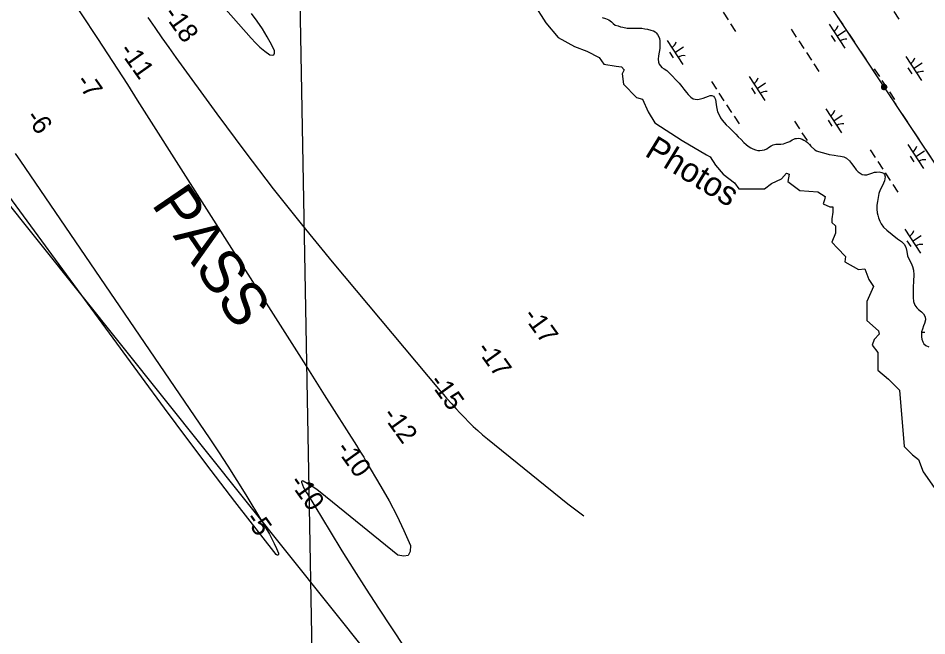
# Model space of a CAD drawing. Extents: x 3945642 to 3966284, y 206476 to 228921.
# Drawn here: x 3956476 to 3958060, y 216052 to 217128 of the extents above; entities that cross this region are included whole.
import ezdxf

# ---------------------------------------------------------------- set-up
doc = ezdxf.new("R2010")
doc.units = 0
for name, color, linetype in [('V-GRID-MAJR', 7, 'Continuous'), ('V-RIVR-EDGE', 7, 'Continuous'), ('V-RIVR-IDEN', 7, 'Continuous'), ('V-RIVR-RANG', 7, 'Continuous'), ('V-TOPO-DPTH', 7, 'Continuous'), ('V-TOPO-MINR', 7, 'Continuous'), ('V-UTIL-LINE', 7, 'Continuous'), ('V-WETL-SWMP', 7, 'Continuous')]:
    doc.layers.add(name, color=color, linetype=linetype)

msp = doc.modelspace()

# ---------------------------------------------------------------- linework, layer by layer
at = {"layer": 'V-GRID-MAJR'}
msp.add_spline([(3957114.3, 209221.5), (3957056.9, 212329.8), (3956944.9, 218389.8), (3956833, 224449.7), (3956787.8, 226894.5)], degree=3, dxfattribs=at)
at = {"layer": 'V-RIVR-EDGE'}
msp.add_lwpolyline([(3957374.4, 217153.2), (3957395.8, 217120), (3957417.2, 217093.9), (3957445.7, 217078.4), (3957467, 217070.1), (3957488.4, 217059.4), (3957496.7, 217047.6), (3957518.1, 217044), (3957527.6, 217042.8), (3957532.3, 217038.1), (3957528.8, 217031), (3957531.2, 217013.1), (3957553.7, 216989.4), (3957564.4, 216987), (3957573.9, 216964.5), (3957585.8, 216945.5), (3957633.3, 216914.6), (3957676, 216889.7), (3957681.9, 216886.1), (3957691.4, 216871.9), (3957704.5, 216856.4), (3957724.7, 216841), (3957731.8, 216830.3), (3957776.9, 216830.3), (3957788.8, 216839.8), (3957806.6, 216848.1), (3957814.9, 216857.6), (3957819.6, 216856.4), (3957817.3, 216843.4), (3957838.6, 216827.9), (3957869.5, 216825.6), (3957882.6, 216817.3), (3957881.4, 216811.3), (3957879, 216804.2), (3957890.9, 216799.4), (3957895.6, 216799.4), (3957895.6, 216789.9), (3957894.4, 216778.1), (3957894.4, 216772.1), (3957900.4, 216766.2), (3957900.4, 216753.1), (3957900.4, 216753.1), (3957894.4, 216737.7), (3957903.9, 216727), (3957918.2, 216712.8), (3957917, 216703.3), (3957940.7, 216690.2), (3957951.4, 216691.4), (3957958.6, 216672.4), (3957966.9, 216660.5), (3957955, 216634.4), (3957955, 216601.2), (3957975.2, 216583.4), (3957976.4, 216577.4), (3957968.1, 216567.9), (3957964.5, 216558.4), (3957974, 216545.4), (3957974, 216527.6), (3957974, 216514.5), (3957993, 216499.1), (3958012, 216480.1), (3958020.3, 216381.5), (3958034.5, 216367.3), (3958045.2, 216359), (3958053.5, 216337.6), (3958072.5, 216310.3)], dxfattribs=at)
at = {"layer": 'V-TOPO-DPTH'}
msp.add_line((3957463.9, 215548.9), (3955413.9, 218111.3), dxfattribs=at)
for points in [[(3956500.5, 217265.1), (3956614.5, 217092.2), (3956632, 217065.5), (3956649.4, 217038.9), (3956666.6, 217012.1), (3956683.7, 216985.2), (3956880.3, 216675.7), (3956912.6, 216624.8), (3956945, 216573.8), (3956977.3, 216522.9), (3957009.6, 216471.9), (3957065.8, 216383.3), (3957070, 216376.6), (3957074.2, 216369.9), (3957078.3, 216363.2), (3957082.3, 216356.4), (3957108.4, 216312.2), (3957122.5, 216287.1), (3957136, 216261.6), (3957148.5, 216235.6), (3957160.2, 216209.3), (3957159.3, 216199), (3957155.6, 216192.2), (3957148.1, 216190.6), (3957137.9, 216192.5), (3957002.3, 216302.5), (3956997, 216306.6), (3956991.5, 216310.5), (3956985.9, 216314), (3956980.1, 216317.4), (3956972.6, 216321.6), (3956971.4, 216321.7), (3956970.5, 216321.4), (3956970, 216320.6), (3956969.9, 216319.4), (3956971.5, 216314.9), (3956973.6, 216310.6), (3956977.8, 216303.1), (3956978.2, 216302.3), (3956979.1, 216300.7), (3956979.6, 216300), (3957019.7, 216233.9), (3957040.4, 216200.3), (3957061.3, 216166.8), (3957082.7, 216133.5), (3957104.3, 216100.4), (3957397.5, 215656.7)], [(3956838.4, 217142.7), (3956882.1, 217093.1), (3956889.6, 217085.1), (3956897.5, 217077.4), (3956905.9, 217070.4), (3956914.7, 217063.7), (3956918.7, 217063.2), (3956921.6, 217064), (3956922.8, 217066.7), (3956923, 217070.7), (3956918.2, 217080.6), (3956910.4, 217095.2), (3956902, 217109.3), (3956892.6, 217122.8), (3956882.6, 217135.9)]]:
    msp.add_lwpolyline(points, dxfattribs=at)
at = {"layer": 'V-TOPO-MINR'}
for points in [[(3956500.5, 217265.1), (3956614.5, 217092.2), (3956632, 217065.5), (3956649.4, 217038.9), (3956666.6, 217012.1), (3956683.7, 216985.2), (3956880.3, 216675.7), (3956912.6, 216624.8), (3956945, 216573.8), (3956977.3, 216522.9), (3957009.6, 216471.9), (3957065.8, 216383.3), (3957070, 216376.6), (3957074.2, 216369.9), (3957078.3, 216363.2), (3957082.3, 216356.4), (3957108.4, 216312.2), (3957122.5, 216287.1), (3957136, 216261.6), (3957148.5, 216235.6), (3957160.2, 216209.3), (3957159.3, 216199), (3957155.6, 216192.2), (3957148.1, 216190.6), (3957137.9, 216192.5), (3957002.3, 216302.5), (3956997, 216306.6), (3956991.5, 216310.5), (3956985.9, 216314), (3956980.1, 216317.4), (3956972.6, 216321.6), (3956971.4, 216321.7), (3956970.5, 216321.4), (3956970, 216320.6), (3956969.9, 216319.4), (3956971.5, 216314.9), (3956973.6, 216310.6), (3956977.8, 216303.1), (3956978.2, 216302.3), (3956979.1, 216300.7), (3956979.6, 216300), (3957019.7, 216233.9), (3957040.4, 216200.3), (3957061.3, 216166.8), (3957082.7, 216133.5), (3957104.3, 216100.4), (3957397.5, 215656.7)], [(3956838.4, 217142.7), (3956882.1, 217093.1), (3956889.6, 217085.1), (3956897.5, 217077.4), (3956905.9, 217070.4), (3956914.7, 217063.7), (3956918.7, 217063.2), (3956921.6, 217064), (3956922.8, 217066.7), (3956923, 217070.7), (3956918.2, 217080.6), (3956910.4, 217095.2), (3956902, 217109.3), (3956892.6, 217122.8), (3956882.6, 217135.9)], [(3956702.4, 217128.9), (3956714.3, 217111.3), (3956726.4, 217093.8), (3956738.6, 217076.5), (3956751, 217059.2), (3956822.3, 216961.3), (3956871.1, 216895.7), (3956920.8, 216830.8), (3956971.8, 216766.9), (3957023.6, 216703.7), (3957211.8, 216478.8), (3957214.5, 216475.6), (3957217.2, 216472.4), (3957220, 216469.3), (3957222.8, 216466.1), (3957231.7, 216456.1), (3957239, 216448), (3957246.4, 216440), (3957254, 216432.2), (3957261.6, 216424.4), (3957269.4, 216416.8), (3957277.4, 216409.4), (3957285.6, 216402.3), (3957293.9, 216395.3), (3957434.3, 216282.2), (3957455, 216266.4), (3957462.1, 216261.3)], [(3956903.4, 216247.6), (3956904.8, 216245.1), (3956906.3, 216242.7), (3956914, 216229), (3956918.4, 216220.9), (3956922.5, 216212.7), (3956926.4, 216204.3), (3956930, 216195.9), (3956929.6, 216193.9), (3956928.9, 216192.7), (3956927.4, 216192.6), (3956925.6, 216193.4), (3956854, 216286.2), (3956812.8, 216340), (3956771.8, 216394.1), (3956731.2, 216448.4), (3956690.9, 216503), (3956367, 216944.4)], [(3956470.8, 216892.3), (3956480.5, 216878.7), (3956809, 216396.7), (3956825.4, 216372.3), (3956841.5, 216347.7), (3956857.3, 216322.8), (3956872.8, 216297.8), (3956900.5, 216252.4), (3956902, 216250), (3956903.4, 216247.6)]]:
    msp.add_lwpolyline(points, dxfattribs=at)
at = {"layer": 'V-UTIL-LINE'}
for points in [[(3958881.3, 222827.3), (3957109.9, 218327), (3961480.2, 211741.6)], [(3957903.7, 217130.8), (3957913.1, 217116.6)], [(3957924.2, 217100), (3957933.6, 217085.8)], [(3957944.6, 217069.1), (3957954, 217055)], [(3957965.1, 217038.3), (3957974.5, 217024.1)], [(3957985.3, 217007.9), (3957985.8, 217009.2), (3957984.7, 217009), (3957984.2, 217007.7), (3957985.1, 217006.6), (3957986.6, 217007.4), (3957987.1, 217009.7), (3957985.3, 217010.8), (3957983, 217010.1), (3957982.4, 217007.9), (3957983.2, 217005.8), (3957985.5, 217005.1), (3957987.9, 217006.5), (3957989, 217010.4), (3957987.8, 217011.6), (3957986.2, 217012.3), (3957984.4, 217012.3), (3957982.8, 217011.7), (3957981.5, 217010.4), (3957980.9, 217008.8), (3957980.8, 217007), (3957981.5, 217005.4), (3957982.8, 217004.2), (3957984.4, 217003.5), (3957986.1, 217003.5), (3957987.8, 217004.2), (3957989, 217005.4), (3957989.7, 217007), (3957989.7, 217008.8), (3957989, 217010.4)], [(3957996, 216991.6), (3958005.4, 216977.5)], [(3958016.5, 216960.8), (3958025.9, 216946.6)], [(3958037, 216930), (3958046.4, 216915.8)], [(3958057.4, 216899.1), (3958066.8, 216885)]]:
    msp.add_lwpolyline(points, dxfattribs=at)
at = {"layer": 'V-WETL-SWMP'}
for p, q in [((3957704.6, 217138.2), (3957713.4, 217124.8)), ((3958002, 217139.3), (3958010.8, 217125.9)), ((3957493.7, 217129), (3957499.7, 217127.4)), ((3957499.7, 217127.4), (3957505.4, 217124.9)), ((3957505.4, 217124.9), (3957509.9, 217121.3)), ((3957509.9, 217121.3), (3957513.3, 217118.3)), ((3957513.3, 217118.3), (3957516.6, 217115.9)), ((3957717.7, 217118.1), (3957726.5, 217104.7)), ((3957516.6, 217115.9), (3957521.5, 217114.2)), ((3957521.5, 217114.2), (3957525.6, 217113)), ((3957525.6, 217113), (3957529.8, 217112)), ((3957529.8, 217112), (3957537.7, 217110.5)), ((3957537.7, 217110.5), (3957556.9, 217110.4)), ((3957556.9, 217110.4), (3957563.1, 217110.2)), ((3957563.1, 217110.2), (3957568.2, 217109.4)), ((3957568.2, 217109.4), (3957572.8, 217108.5)), ((3957572.8, 217108.5), (3957578.5, 217107)), ((3957578.5, 217107), (3957583.1, 217105.6)), ((3957583.1, 217105.6), (3957586.4, 217104.1)), ((3957586.4, 217104.1), (3957588, 217102.5)), ((3957588, 217102.5), (3957590.3, 217099.2)), ((3957823.4, 217108.4), (3957832.2, 217095)), ((3957889.2, 217117.5), (3957916.6, 217075.7)), ((3957902.9, 217096.6), (3957918, 217106.5)), ((3957590.3, 217099.2), (3957592.4, 217095.4)), ((3957592.4, 217095.4), (3957593.9, 217092.2)), ((3957593.9, 217092.2), (3957594.5, 217088.2)), ((3957594.5, 217088.2), (3957594.6, 217082.5)), ((3957607, 217088.9), (3957634.4, 217047.1)), ((3957836.6, 217088.3), (3957845.3, 217074.9)), ((3957893.2, 217097.4), (3957899.7, 217087.4)), ((3957594.4, 217074.8), (3957593.5, 217068.6)), ((3957594.6, 217082.5), (3957594.4, 217074.8)), ((3957620.7, 217068), (3957635.8, 217077.9)), ((3957592, 217062.2), (3957591.4, 217056.5)), ((3957591.4, 217056.5), (3957591.9, 217051.4)), ((3957593.5, 217068.6), (3957592, 217062.2)), ((3957611, 217068.8), (3957617.5, 217058.8)), ((3957849.7, 217068.3), (3957858.5, 217054.9)), ((3958022.8, 217061.3), (3958050.2, 217019.5)), ((3957591.9, 217051.4), (3957593.2, 217047.7)), ((3957593.2, 217047.7), (3957595.4, 217044.7)), ((3957595.4, 217044.7), (3957598.1, 217042.2)), ((3957598.1, 217042.2), (3957601.8, 217039.7)), ((3957601.8, 217039.7), (3957606.4, 217036.6)), ((3957862.9, 217048.2), (3957871.6, 217034.8)), ((3957968.1, 217039.5), (3957976.9, 217026.1)), ((3958026.8, 217041.2), (3958033.3, 217031.1)), ((3958036.5, 217040.4), (3958051.6, 217050.3)), ((3957606.4, 217036.6), (3957610.3, 217033.4)), ((3957610.3, 217033.4), (3957628, 217014.9)), ((3957750.1, 217026.4), (3957777.5, 216984.6)), ((3957628, 217014.9), (3957632.8, 217008.9)), ((3957632.8, 217008.9), (3957636.3, 217004.2)), ((3957684.3, 217017.3), (3957693, 217003.9)), ((3957763.8, 217005.5), (3957778.8, 217015.3)), ((3957981.3, 217019.4), (3957990, 217006)), ((3957636.3, 217004.2), (3957640.6, 216998.6)), ((3957640.6, 216998.6), (3957644, 216994.6)), ((3957644, 216994.6), (3957648.4, 216990.2)), ((3957674.6, 216990.2), (3957679.1, 216992.1)), ((3957679.1, 216992.1), (3957682.2, 216993.1)), ((3957682.2, 216993.1), (3957685.3, 216993.1)), ((3957685.3, 216993.1), (3957687.8, 216992.2)), ((3957687.8, 216992.2), (3957689.9, 216989.7)), ((3957697.4, 216997.2), (3957706.2, 216983.8)), ((3957754, 217006.3), (3957760.6, 216996.2)), ((3957994.4, 216999.3), (3958003.2, 216985.9)), ((3957648.4, 216990.2), (3957652.6, 216987.6)), ((3957652.6, 216987.6), (3957656.1, 216986.6)), ((3957656.1, 216986.6), (3957660.7, 216986.4)), ((3957660.7, 216986.4), (3957665.5, 216987.1)), ((3957665.5, 216987.1), (3957670, 216988.3)), ((3957670, 216988.3), (3957674.6, 216990.2)), ((3957689.9, 216989.7), (3957691.3, 216986.1)), ((3957691.3, 216986.1), (3957692.2, 216981.9)), ((3957692.2, 216981.9), (3957692.7, 216976.7)), ((3957692.7, 216976.7), (3957693.5, 216970.4)), ((3957710.6, 216977.1), (3957719.4, 216963.7)), ((3957693.5, 216970.4), (3957695.1, 216964.5)), ((3957695.1, 216964.5), (3957697.7, 216959.3)), ((3957883.7, 216970.1), (3957911.1, 216928.3)), ((3957697.7, 216959.3), (3957700.2, 216954.1)), ((3957700.2, 216954.1), (3957703.2, 216950.1)), ((3957703.2, 216950.1), (3957706.5, 216946.3)), ((3957706.5, 216946.3), (3957710.2, 216942.3)), ((3957723.7, 216957), (3957732.5, 216943.6)), ((3957829, 216948.3), (3957837.7, 216934.9)), ((3957887.6, 216950), (3957894.2, 216940)), ((3957897.4, 216949.2), (3957912.4, 216959.1)), ((3957710.2, 216942.3), (3957715.4, 216937.2)), ((3957715.4, 216937.2), (3957721.7, 216931.3)), ((3957721.7, 216931.3), (3957727.1, 216925.8)), ((3957842.1, 216928.2), (3957850.9, 216914.9)), ((3957727.1, 216925.8), (3957731.1, 216921.4)), ((3957731.1, 216921.4), (3957735.9, 216916.3)), ((3957735.9, 216916.3), (3957740.5, 216911.4)), ((3957815.8, 216911), (3957820.7, 216913.2)), ((3957820.7, 216913.2), (3957825.1, 216915.8)), ((3957825.1, 216915.8), (3957828, 216917.3)), ((3957828, 216917.3), (3957830.1, 216918)), ((3957830.1, 216918), (3957832.7, 216918.5)), ((3957832.7, 216918.5), (3957835.4, 216918.8)), ((3957835.4, 216918.8), (3957838.7, 216918.3)), ((3957838.7, 216918.3), (3957842.6, 216917)), ((3957842.6, 216917), (3957845.5, 216915.5)), ((3957845.5, 216915.5), (3957848.7, 216913.5)), ((3957848.7, 216913.5), (3957852, 216911.1)), ((3957740.5, 216911.4), (3957744.6, 216907.8)), ((3957744.6, 216907.8), (3957748.3, 216904.9)), ((3957748.3, 216904.9), (3957752.7, 216902)), ((3957752.7, 216902), (3957756.7, 216900.3)), ((3957756.7, 216900.3), (3957761.2, 216898.7)), ((3957761.2, 216898.7), (3957765.4, 216897.4)), ((3957765.4, 216897.4), (3957768.7, 216897.3)), ((3957768.7, 216897.3), (3957772.8, 216897.7)), ((3957772.8, 216897.7), (3957776.8, 216898.6)), ((3957776.8, 216898.6), (3957780.6, 216900.3)), ((3957780.6, 216900.3), (3957784, 216902.5)), ((3957784, 216902.5), (3957788.2, 216905.2)), ((3957788.2, 216905.2), (3957791.9, 216907.3)), ((3957791.9, 216907.3), (3957796.3, 216908.4)), ((3957796.3, 216908.4), (3957800, 216908.3)), ((3957800, 216908.3), (3957805.1, 216908.1)), ((3957805.1, 216908.1), (3957810, 216908.9)), ((3957810, 216908.9), (3957815.8, 216911)), ((3957852, 216911.1), (3957855, 216907.8)), ((3957855, 216907.8), (3957857.8, 216905)), ((3957855.3, 216908.2), (3957856.4, 216906.4)), ((3957857.8, 216905), (3957864.7, 216898.4)), ((3957864.7, 216898.4), (3957867.2, 216896.9)), ((3957867.2, 216896.9), (3957871.1, 216895.4)), ((3957960.9, 216898.5), (3957969.7, 216885.1)), ((3958026.7, 216907.6), (3958054.1, 216865.8)), ((3958040.4, 216886.7), (3958055.5, 216896.6)), ((3957871.1, 216895.4), (3957877, 216893.7)), ((3957877, 216893.7), (3957883.5, 216891.9)), ((3957883.5, 216891.9), (3957889.7, 216890.5)), ((3957889.7, 216890.5), (3957898.2, 216889.1)), ((3957898.2, 216889.1), (3957904.6, 216888.3)), ((3957904.6, 216888.3), (3957909.3, 216887.7)), ((3957909.3, 216887.7), (3957914.8, 216886.3)), ((3957914.8, 216886.3), (3957919.7, 216884)), ((3957919.7, 216884), (3957924.9, 216879.1)), ((3958030.7, 216887.5), (3958037.3, 216877.4)), ((3957924.9, 216879.1), (3957928.3, 216874.6)), ((3957928.3, 216874.6), (3957932.3, 216869.4)), ((3957932.3, 216869.4), (3957936.7, 216863.9)), ((3957974.1, 216878.4), (3957982.9, 216865)), ((3957936.7, 216863.9), (3957939.9, 216860.3)), ((3957939.9, 216860.3), (3957943.4, 216857.6)), ((3957943.4, 216857.6), (3957947.1, 216855.8)), ((3957947.1, 216855.8), (3957950.9, 216854.8)), ((3957950.9, 216854.8), (3957955.4, 216855.1)), ((3957955.4, 216855.1), (3957960.3, 216856.5)), ((3957960.3, 216856.5), (3957964, 216858.1)), ((3957964, 216858.1), (3957968.3, 216859.4)), ((3957968.3, 216859.4), (3957971.7, 216859.8)), ((3957971.7, 216859.8), (3957976.7, 216860.4)), ((3957976.7, 216860.4), (3957981.3, 216859.3)), ((3957981.3, 216859.3), (3957984.1, 216858)), ((3957984.1, 216858), (3957986.1, 216855.5)), ((3957987, 216851.5), (3957985.7, 216844.3)), ((3957986.1, 216855.5), (3957987, 216851.5)), ((3957987.2, 216858.3), (3957996, 216844.9)), ((3957982.5, 216836.6), (3957978.5, 216828.9)), ((3957985.7, 216844.3), (3957982.5, 216836.6)), ((3958000.4, 216838.3), (3958009.2, 216824.9)), ((3957976.2, 216822.2), (3957974.8, 216815.6)), ((3957978.5, 216828.9), (3957976.2, 216822.2)), ((3957973.6, 216808.8), (3957972.6, 216801.9)), ((3957972.6, 216801.9), (3957972.7, 216795.1)), ((3957974.8, 216815.6), (3957973.6, 216808.8)), ((3957972.7, 216795.1), (3957973.4, 216788.5)), ((3957973.4, 216788.5), (3957974.3, 216784.5)), ((3957974.3, 216784.5), (3957975.6, 216780.1)), ((3957975.6, 216780.1), (3957977.8, 216774.5)), ((3957977.8, 216774.5), (3957980.3, 216769.6)), ((3957980.3, 216769.6), (3957984.3, 216764.1)), ((3957984.3, 216764.1), (3957990.1, 216758.3)), ((3957990.1, 216758.3), (3958008.5, 216743.6)), ((3958021.2, 216760.2), (3958048.6, 216718.4)), ((3958008.5, 216743.6), (3958015.7, 216738.8)), ((3958015.7, 216738.8), (3958020.2, 216734.3)), ((3958025.1, 216740.1), (3958031.7, 216730.1)), ((3958034.9, 216739.3), (3958049.9, 216749.2)), ((3958020.2, 216734.3), (3958023.3, 216729.1)), ((3958023.3, 216729.1), (3958024.9, 216721.6)), ((3958024.9, 216721.6), (3958025.9, 216714.1)), ((3958025.9, 216714.1), (3958029.2, 216706.2)), ((3958029.2, 216706.2), (3958032.4, 216701.1)), ((3958032.4, 216701.1), (3958034.9, 216695.1)), ((3958034.9, 216695.1), (3958036.4, 216688.7)), ((3958036.4, 216688.7), (3958036.9, 216680.6)), ((3958036.9, 216680.6), (3958036.4, 216669.5)), ((3958036, 216659.1), (3958035.9, 216641.3)), ((3958036.4, 216669.5), (3958036, 216659.1)), ((3958035.9, 216641.3), (3958036.6, 216634.4)), ((3958036.6, 216634.4), (3958038.9, 216627.8)), ((3958038.9, 216627.8), (3958042.1, 216623.1)), ((3958042.1, 216623.1), (3958044.9, 216620.3)), ((3958044.9, 216620.3), (3958050.2, 216616.2)), ((3958050.2, 216616.2), (3958054.1, 216612.6)), ((3958054.1, 216612.6), (3958057, 216607.4)), ((3958055.7, 216596.1), (3958053.9, 216591.7)), ((3958057.4, 216602.2), (3958055.7, 216596.1)), ((3958057, 216607.4), (3958057.4, 216602.2)), ((3958050.6, 216581.7), (3958050.2, 216577.5)), ((3958052, 216586.3), (3958050.6, 216581.7)), ((3958053.9, 216591.7), (3958052, 216586.3)), ((3958050.2, 216577.5), (3958050.2, 216572.8)), ((3958050.2, 216572.8), (3958050.8, 216568.9)), ((3958050.8, 216568.9), (3958052.9, 216564.2)), ((3958052.9, 216564.2), (3958054.7, 216560.6)), ((3958054.7, 216560.6), (3958057.7, 216557.7)), ((3958057.7, 216557.7), (3958062.9, 216555.2))]:
    msp.add_line(p, q, dxfattribs=at)
for centre, start, end in [((3957888, 217119.8), 302.4575, 344.0011), ((3957605.8, 217091.2), 302.4575, 344.0011), ((3957918.2, 217073.6), 82.4574, 124.0011), ((3957636, 217045), 82.4574, 124.0011), ((3958021.6, 217063.6), 302.4575, 344.0011), ((3957748.8, 217028.7), 302.4575, 344.0011), ((3958051.8, 217017.4), 82.4574, 124.0011), ((3957779.1, 216982.5), 82.4574, 124.0011), ((3957882.4, 216972.5), 302.4575, 344.0011), ((3957912.7, 216926.3), 82.4574, 124.0011), ((3958025.5, 216909.9), 302.4575, 344.0011), ((3958055.8, 216863.7), 82.4574, 124.0011), ((3958019.9, 216762.6), 302.4575, 344.0011), ((3958050.2, 216716.3), 82.4574, 124.0011), ((3958054.1, 216562.7), 82.4574, 102.174)]:
    msp.add_arc(centre, 17.6, start, end, dxfattribs=at)

# ---------------------------------------------------------------- texts
at = {"layer": 'V-RIVR-IDEN'}
for s, height, rotation, p in [('Photos', 42, 328.5434, (3957566.2, 216889.1)), ('PASS', 75, 304.3169, (3956707.3, 216803.9))]:
    msp.add_text(s, height=height, rotation=rotation, dxfattribs=at).set_placement(p)
at = {"layer": 'V-RIVR-RANG'}
for s, rotation, p in [('-18', 305.2748, (3956728.2, 217135.1)), ('-11', 305.2748, (3956650.8, 217071.4)), ('-7', 305.2748, (3956575.3, 217017.3)), ('-6', 305.2748, (3956487.9, 216955.2)), ('-17', 305.6139, (3957354.7, 216609.4)), ('-17', 305.6139, (3957273.5, 216551.2)), ('-15', 305.6139, (3957191.1, 216494.4)), ('-12', 305.6139, (3957109.5, 216436.6)), ('-10', 305.6139, (3957028.8, 216377.6)), ('-10', 305.6139, (3956947.5, 216319.4)), ('-5', 305.6139, (3956870.4, 216255.2))]:
    msp.add_text(s, height=33.5, rotation=rotation, dxfattribs=at).set_placement(p)

doc.saveas('drawing.dxf')
